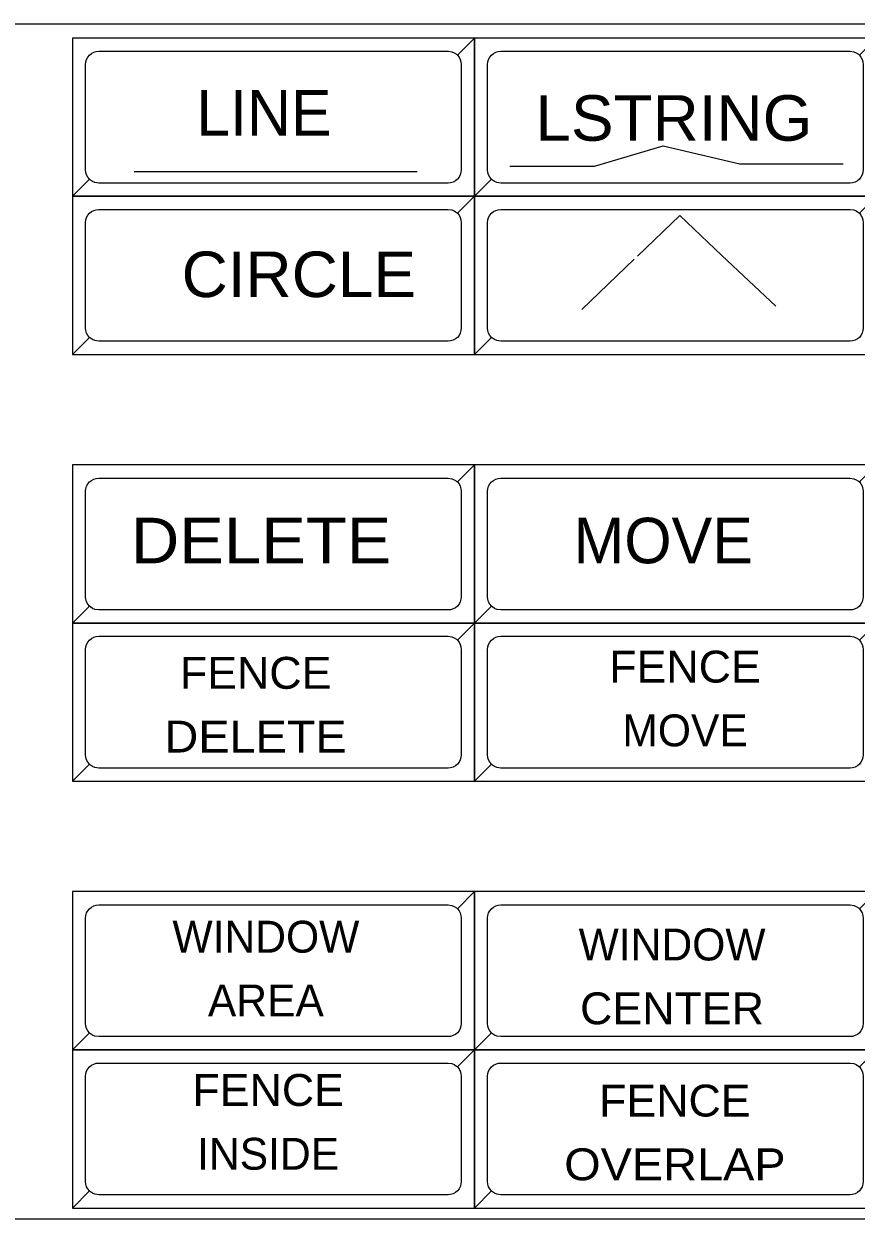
# Model space of a CAD drawing. Extents: x 16898 to 16911.6, y 15837.8 to 15842.
# Drawn here: x 16902.962 to 16904.383, y 15839.972 to 15842.012 of the extents above; entities that cross this region are included whole.
import ezdxf
from ezdxf.enums import TextEntityAlignment as Align

# ---------------------------------------------------------------- set-up
doc = ezdxf.new("R2010")
doc.units = 0
doc.header["$LTSCALE"] = 0.018
doc.linetypes.add('MEDIUM_DASHED', pattern=[4.5, 3, -1.5])
for name, color, linetype, lineweight in [('1', 7, 'Continuous', 25), ('2', 7, 'Continuous', 13), ('5', 7, 'Continuous', 13)]:
    doc.layers.add(name, color=color, linetype=linetype, lineweight=lineweight)

msp = doc.modelspace()

# ---------------------------------------------------------------- linework, layer by layer
at = {"layer": '1'}
for points in [[(16897.9955, 15839.9723), (16897.9955, 15842.0124), (16911.4764, 15842.0124), (16911.5674, 15841.9251), (16911.5674, 15840.0599), (16911.4764, 15839.9723)], [(16903.045, 15841.7183), (16903.7314, 15841.7183), (16903.7314, 15841.9883), (16903.045, 15841.9883)], [(16903.045, 15841.7183), (16903.7314, 15841.7183), (16903.7314, 15841.9883), (16903.7023, 15841.9592), (16903.7051, 15841.9558), (16903.7072, 15841.9519), (16903.7084, 15841.9477), (16903.7089, 15841.9433), (16903.7089, 15841.7633), (16903.7084, 15841.7589), (16903.7072, 15841.7547), (16903.7051, 15841.7508), (16903.7023, 15841.7474), (16903.7023, 15841.7474), (16903.6989, 15841.7446), (16903.695, 15841.7425), (16903.6908, 15841.7412), (16903.6864, 15841.7408), (16903.09, 15841.7408), (16903.0834, 15841.7418), (16903.0794, 15841.7435), (16903.0757, 15841.7459), (16903.0741, 15841.7474)], [(16903.7314, 15841.9883), (16903.045, 15841.9883), (16903.045, 15841.7183), (16903.0741, 15841.7474), (16903.0713, 15841.7508), (16903.0692, 15841.7547), (16903.0679, 15841.7589), (16903.0675, 15841.7633), (16903.0675, 15841.9433), (16903.0679, 15841.9477), (16903.0692, 15841.9519), (16903.0713, 15841.9558), (16903.0741, 15841.9592), (16903.0741, 15841.9592), (16903.0775, 15841.962), (16903.0814, 15841.9641), (16903.0856, 15841.9653), (16903.09, 15841.9658), (16903.6864, 15841.9658), (16903.693, 15841.9648), (16903.697, 15841.9631), (16903.7007, 15841.9607), (16903.7023, 15841.9592)], [(16903.7314, 15841.7183), (16904.4178, 15841.7183), (16904.4178, 15841.9883), (16903.7314, 15841.9883)], [(16903.7314, 15841.7183), (16904.4178, 15841.7183), (16904.4178, 15841.9883), (16904.3887, 15841.9592), (16904.3915, 15841.9558), (16904.3936, 15841.9519), (16904.3948, 15841.9477), (16904.3953, 15841.9433), (16904.3953, 15841.7633), (16904.3948, 15841.7589), (16904.3936, 15841.7547), (16904.3915, 15841.7508), (16904.3887, 15841.7474), (16904.3887, 15841.7474), (16904.3853, 15841.7446), (16904.3814, 15841.7425), (16904.3772, 15841.7412), (16904.3728, 15841.7408), (16903.7764, 15841.7408), (16903.7698, 15841.7418), (16903.7658, 15841.7435), (16903.7621, 15841.7459), (16903.7605, 15841.7474)], [(16904.4178, 15841.9883), (16903.7314, 15841.9883), (16903.7314, 15841.7183), (16903.7605, 15841.7474), (16903.7577, 15841.7508), (16903.7556, 15841.7547), (16903.7543, 15841.7589), (16903.7539, 15841.7633), (16903.7539, 15841.9433), (16903.7543, 15841.9477), (16903.7556, 15841.9519), (16903.7577, 15841.9558), (16903.7605, 15841.9592), (16903.7605, 15841.9592), (16903.7639, 15841.962), (16903.7678, 15841.9641), (16903.772, 15841.9653), (16903.7764, 15841.9658), (16904.3728, 15841.9658), (16904.3794, 15841.9648), (16904.3834, 15841.9631), (16904.3871, 15841.9607), (16904.3887, 15841.9592)], [(16903.045, 15841.4483), (16903.7314, 15841.4483), (16903.7314, 15841.7183), (16903.045, 15841.7183)], [(16903.045, 15841.4483), (16903.7314, 15841.4483), (16903.7314, 15841.7183), (16903.7023, 15841.6892), (16903.7051, 15841.6858), (16903.7072, 15841.6819), (16903.7084, 15841.6777), (16903.7089, 15841.6733), (16903.7089, 15841.4933), (16903.7084, 15841.4889), (16903.7072, 15841.4847), (16903.7051, 15841.4808), (16903.7023, 15841.4774), (16903.7023, 15841.4774), (16903.6989, 15841.4746), (16903.695, 15841.4725), (16903.6908, 15841.4712), (16903.6864, 15841.4708), (16903.09, 15841.4708), (16903.0834, 15841.4718), (16903.0794, 15841.4735), (16903.0757, 15841.4759), (16903.0741, 15841.4774)], [(16903.7314, 15841.7183), (16903.045, 15841.7183), (16903.045, 15841.4483), (16903.0741, 15841.4774), (16903.0713, 15841.4808), (16903.0692, 15841.4847), (16903.0679, 15841.4889), (16903.0675, 15841.4933), (16903.0675, 15841.6733), (16903.0679, 15841.6777), (16903.0692, 15841.6819), (16903.0713, 15841.6858), (16903.0741, 15841.6892), (16903.0741, 15841.6892), (16903.0775, 15841.692), (16903.0814, 15841.6941), (16903.0856, 15841.6953), (16903.09, 15841.6958), (16903.6864, 15841.6958), (16903.693, 15841.6948), (16903.697, 15841.6931), (16903.7007, 15841.6907), (16903.7023, 15841.6892)], [(16903.7314, 15841.4483), (16904.4178, 15841.4483), (16904.4178, 15841.7183), (16903.7314, 15841.7183)], [(16903.7314, 15841.4483), (16904.4178, 15841.4483), (16904.4178, 15841.7183), (16904.3887, 15841.6892), (16904.3915, 15841.6858), (16904.3936, 15841.6819), (16904.3948, 15841.6777), (16904.3953, 15841.6733), (16904.3953, 15841.4933), (16904.3948, 15841.4889), (16904.3936, 15841.4847), (16904.3915, 15841.4808), (16904.3887, 15841.4774), (16904.3887, 15841.4774), (16904.3853, 15841.4746), (16904.3814, 15841.4725), (16904.3772, 15841.4712), (16904.3728, 15841.4708), (16903.7764, 15841.4708), (16903.7698, 15841.4718), (16903.7658, 15841.4735), (16903.7621, 15841.4759), (16903.7605, 15841.4774)], [(16904.4178, 15841.7183), (16903.7314, 15841.7183), (16903.7314, 15841.4483), (16903.7605, 15841.4774), (16903.7577, 15841.4808), (16903.7556, 15841.4847), (16903.7543, 15841.4889), (16903.7539, 15841.4933), (16903.7539, 15841.6733), (16903.7543, 15841.6777), (16903.7556, 15841.6819), (16903.7577, 15841.6858), (16903.7605, 15841.6892), (16903.7605, 15841.6892), (16903.7639, 15841.692), (16903.7678, 15841.6941), (16903.772, 15841.6953), (16903.7764, 15841.6958), (16904.3728, 15841.6958), (16904.3794, 15841.6948), (16904.3834, 15841.6931), (16904.3871, 15841.6907), (16904.3887, 15841.6892)], [(16903.045, 15840.9896), (16903.7314, 15840.9896), (16903.7314, 15841.2596), (16903.045, 15841.2596)], [(16903.045, 15840.9896), (16903.7314, 15840.9896), (16903.7314, 15841.2596), (16903.7023, 15841.2305), (16903.7051, 15841.2271), (16903.7072, 15841.2232), (16903.7084, 15841.219), (16903.7089, 15841.2146), (16903.7089, 15841.0346), (16903.7084, 15841.0302), (16903.7072, 15841.026), (16903.7051, 15841.0221), (16903.7023, 15841.0187), (16903.7023, 15841.0187), (16903.6989, 15841.0159), (16903.695, 15841.0138), (16903.6908, 15841.0125), (16903.6864, 15841.0121), (16903.09, 15841.0121), (16903.0834, 15841.0131), (16903.0794, 15841.0148), (16903.0757, 15841.0172), (16903.0741, 15841.0187)], [(16903.7314, 15841.2596), (16903.045, 15841.2596), (16903.045, 15840.9896), (16903.0741, 15841.0187), (16903.0713, 15841.0221), (16903.0692, 15841.026), (16903.0679, 15841.0302), (16903.0675, 15841.0346), (16903.0675, 15841.2146), (16903.0679, 15841.219), (16903.0692, 15841.2232), (16903.0713, 15841.2271), (16903.0741, 15841.2305), (16903.0741, 15841.2305), (16903.0775, 15841.2333), (16903.0814, 15841.2354), (16903.0856, 15841.2366), (16903.09, 15841.2371), (16903.6864, 15841.2371), (16903.693, 15841.2361), (16903.697, 15841.2344), (16903.7007, 15841.232), (16903.7023, 15841.2305)], [(16903.7314, 15840.9896), (16904.4178, 15840.9896), (16904.4178, 15841.2596), (16903.7314, 15841.2596)], [(16903.7314, 15840.9896), (16904.4178, 15840.9896), (16904.4178, 15841.2596), (16904.3887, 15841.2305), (16904.3915, 15841.2271), (16904.3936, 15841.2232), (16904.3948, 15841.219), (16904.3953, 15841.2146), (16904.3953, 15841.0346), (16904.3948, 15841.0302), (16904.3936, 15841.026), (16904.3915, 15841.0221), (16904.3887, 15841.0187), (16904.3887, 15841.0187), (16904.3853, 15841.0159), (16904.3814, 15841.0138), (16904.3772, 15841.0125), (16904.3728, 15841.0121), (16903.7764, 15841.0121), (16903.7698, 15841.0131), (16903.7658, 15841.0148), (16903.7621, 15841.0172), (16903.7605, 15841.0187)], [(16904.4178, 15841.2596), (16903.7314, 15841.2596), (16903.7314, 15840.9896), (16903.7605, 15841.0187), (16903.7577, 15841.0221), (16903.7556, 15841.026), (16903.7543, 15841.0302), (16903.7539, 15841.0346), (16903.7539, 15841.2146), (16903.7543, 15841.219), (16903.7556, 15841.2232), (16903.7577, 15841.2271), (16903.7605, 15841.2305), (16903.7605, 15841.2305), (16903.7639, 15841.2333), (16903.7678, 15841.2354), (16903.772, 15841.2366), (16903.7764, 15841.2371), (16904.3728, 15841.2371), (16904.3794, 15841.2361), (16904.3834, 15841.2344), (16904.3871, 15841.232), (16904.3887, 15841.2305)], [(16903.045, 15840.7196), (16903.7314, 15840.7196), (16903.7314, 15840.9896), (16903.045, 15840.9896)], [(16903.045, 15840.7196), (16903.7314, 15840.7196), (16903.7314, 15840.9896), (16903.7023, 15840.9605), (16903.7051, 15840.9571), (16903.7072, 15840.9532), (16903.7084, 15840.949), (16903.7089, 15840.9446), (16903.7089, 15840.7646), (16903.7084, 15840.7602), (16903.7072, 15840.756), (16903.7051, 15840.7521), (16903.7023, 15840.7487), (16903.7023, 15840.7487), (16903.6989, 15840.7459), (16903.695, 15840.7438), (16903.6908, 15840.7425), (16903.6864, 15840.7421), (16903.09, 15840.7421), (16903.0834, 15840.7431), (16903.0794, 15840.7448), (16903.0757, 15840.7472), (16903.0741, 15840.7487)], [(16903.7314, 15840.9896), (16903.045, 15840.9896), (16903.045, 15840.7196), (16903.0741, 15840.7487), (16903.0713, 15840.7521), (16903.0692, 15840.756), (16903.0679, 15840.7602), (16903.0675, 15840.7646), (16903.0675, 15840.9446), (16903.0679, 15840.949), (16903.0692, 15840.9532), (16903.0713, 15840.9571), (16903.0741, 15840.9605), (16903.0741, 15840.9605), (16903.0775, 15840.9633), (16903.0814, 15840.9654), (16903.0856, 15840.9666), (16903.09, 15840.9671), (16903.6864, 15840.9671), (16903.693, 15840.9661), (16903.697, 15840.9644), (16903.7007, 15840.962), (16903.7023, 15840.9605)], [(16903.7314, 15840.7196), (16904.4178, 15840.7196), (16904.4178, 15840.9896), (16903.7314, 15840.9896)], [(16903.7314, 15840.7196), (16904.4178, 15840.7196), (16904.4178, 15840.9896), (16904.3887, 15840.9605), (16904.3915, 15840.9571), (16904.3936, 15840.9532), (16904.3948, 15840.949), (16904.3953, 15840.9446), (16904.3953, 15840.7646), (16904.3948, 15840.7602), (16904.3936, 15840.756), (16904.3915, 15840.7521), (16904.3887, 15840.7487), (16904.3887, 15840.7487), (16904.3853, 15840.7459), (16904.3814, 15840.7438), (16904.3772, 15840.7425), (16904.3728, 15840.7421), (16903.7764, 15840.7421), (16903.7698, 15840.7431), (16903.7658, 15840.7448), (16903.7621, 15840.7472), (16903.7605, 15840.7487)], [(16904.4178, 15840.9896), (16903.7314, 15840.9896), (16903.7314, 15840.7196), (16903.7605, 15840.7487), (16903.7577, 15840.7521), (16903.7556, 15840.756), (16903.7543, 15840.7602), (16903.7539, 15840.7646), (16903.7539, 15840.9446), (16903.7543, 15840.949), (16903.7556, 15840.9532), (16903.7577, 15840.9571), (16903.7605, 15840.9605), (16903.7605, 15840.9605), (16903.7639, 15840.9633), (16903.7678, 15840.9654), (16903.772, 15840.9666), (16903.7764, 15840.9671), (16904.3728, 15840.9671), (16904.3794, 15840.9661), (16904.3834, 15840.9644), (16904.3871, 15840.962), (16904.3887, 15840.9605)], [(16903.045, 15840.2612), (16903.7314, 15840.2612), (16903.7314, 15840.5312), (16903.045, 15840.5312)], [(16903.045, 15840.2612), (16903.7314, 15840.2612), (16903.7314, 15840.5312), (16903.7023, 15840.5021), (16903.7051, 15840.4987), (16903.7072, 15840.4948), (16903.7084, 15840.4906), (16903.7089, 15840.4862), (16903.7089, 15840.3062), (16903.7084, 15840.3018), (16903.7072, 15840.2976), (16903.7051, 15840.2937), (16903.7023, 15840.2903), (16903.7023, 15840.2903), (16903.6989, 15840.2875), (16903.695, 15840.2854), (16903.6908, 15840.2841), (16903.6864, 15840.2837), (16903.09, 15840.2837), (16903.0834, 15840.2847), (16903.0794, 15840.2864), (16903.0757, 15840.2888), (16903.0741, 15840.2903)], [(16903.7314, 15840.5312), (16903.045, 15840.5312), (16903.045, 15840.2612), (16903.0741, 15840.2903), (16903.0713, 15840.2937), (16903.0692, 15840.2976), (16903.0679, 15840.3018), (16903.0675, 15840.3062), (16903.0675, 15840.4862), (16903.0679, 15840.4906), (16903.0692, 15840.4948), (16903.0713, 15840.4987), (16903.0741, 15840.5021), (16903.0741, 15840.5021), (16903.0775, 15840.5049), (16903.0814, 15840.507), (16903.0856, 15840.5082), (16903.09, 15840.5087), (16903.6864, 15840.5087), (16903.693, 15840.5077), (16903.697, 15840.506), (16903.7007, 15840.5036), (16903.7023, 15840.5021)], [(16903.7314, 15840.2612), (16904.4178, 15840.2612), (16904.4178, 15840.5312), (16903.7314, 15840.5312)], [(16903.7314, 15840.2612), (16904.4178, 15840.2612), (16904.4178, 15840.5312), (16904.3887, 15840.5021), (16904.3915, 15840.4987), (16904.3936, 15840.4948), (16904.3948, 15840.4906), (16904.3953, 15840.4862), (16904.3953, 15840.3062), (16904.3948, 15840.3018), (16904.3936, 15840.2976), (16904.3915, 15840.2937), (16904.3887, 15840.2903), (16904.3887, 15840.2903), (16904.3853, 15840.2875), (16904.3814, 15840.2854), (16904.3772, 15840.2841), (16904.3728, 15840.2837), (16903.7764, 15840.2837), (16903.7698, 15840.2847), (16903.7658, 15840.2864), (16903.7621, 15840.2888), (16903.7605, 15840.2903)], [(16904.4178, 15840.5312), (16903.7314, 15840.5312), (16903.7314, 15840.2612), (16903.7605, 15840.2903), (16903.7577, 15840.2937), (16903.7556, 15840.2976), (16903.7543, 15840.3018), (16903.7539, 15840.3062), (16903.7539, 15840.4862), (16903.7543, 15840.4906), (16903.7556, 15840.4948), (16903.7577, 15840.4987), (16903.7605, 15840.5021), (16903.7605, 15840.5021), (16903.7639, 15840.5049), (16903.7678, 15840.507), (16903.772, 15840.5082), (16903.7764, 15840.5087), (16904.3728, 15840.5087), (16904.3794, 15840.5077), (16904.3834, 15840.506), (16904.3871, 15840.5036), (16904.3887, 15840.5021)], [(16903.045, 15839.9912), (16903.7314, 15839.9912), (16903.7314, 15840.2612), (16903.045, 15840.2612)], [(16903.045, 15839.9912), (16903.7314, 15839.9912), (16903.7314, 15840.2612), (16903.7023, 15840.2321), (16903.7051, 15840.2287), (16903.7072, 15840.2248), (16903.7084, 15840.2206), (16903.7089, 15840.2162), (16903.7089, 15840.0362), (16903.7084, 15840.0318), (16903.7072, 15840.0276), (16903.7051, 15840.0237), (16903.7023, 15840.0203), (16903.7023, 15840.0203), (16903.6989, 15840.0175), (16903.695, 15840.0154), (16903.6908, 15840.0141), (16903.6864, 15840.0137), (16903.09, 15840.0137), (16903.0834, 15840.0147), (16903.0794, 15840.0164), (16903.0757, 15840.0188), (16903.0741, 15840.0203)], [(16903.7314, 15840.2612), (16903.045, 15840.2612), (16903.045, 15839.9912), (16903.0741, 15840.0203), (16903.0713, 15840.0237), (16903.0692, 15840.0276), (16903.0679, 15840.0318), (16903.0675, 15840.0362), (16903.0675, 15840.2162), (16903.0679, 15840.2206), (16903.0692, 15840.2248), (16903.0713, 15840.2287), (16903.0741, 15840.2321), (16903.0741, 15840.2321), (16903.0775, 15840.2349), (16903.0814, 15840.237), (16903.0856, 15840.2382), (16903.09, 15840.2387), (16903.6864, 15840.2387), (16903.693, 15840.2377), (16903.697, 15840.236), (16903.7007, 15840.2336), (16903.7023, 15840.2321)], [(16903.7314, 15839.9912), (16904.4178, 15839.9912), (16904.4178, 15840.2612), (16903.7314, 15840.2612)], [(16903.7314, 15839.9912), (16904.4178, 15839.9912), (16904.4178, 15840.2612), (16904.3887, 15840.2321), (16904.3915, 15840.2287), (16904.3936, 15840.2248), (16904.3948, 15840.2206), (16904.3953, 15840.2162), (16904.3953, 15840.0362), (16904.3948, 15840.0318), (16904.3936, 15840.0276), (16904.3915, 15840.0237), (16904.3887, 15840.0203), (16904.3887, 15840.0203), (16904.3853, 15840.0175), (16904.3814, 15840.0154), (16904.3772, 15840.0141), (16904.3728, 15840.0137), (16903.7764, 15840.0137), (16903.7698, 15840.0147), (16903.7658, 15840.0164), (16903.7621, 15840.0188), (16903.7605, 15840.0203)], [(16904.4178, 15840.2612), (16903.7314, 15840.2612), (16903.7314, 15839.9912), (16903.7605, 15840.0203), (16903.7577, 15840.0237), (16903.7556, 15840.0276), (16903.7543, 15840.0318), (16903.7539, 15840.0362), (16903.7539, 15840.2162), (16903.7543, 15840.2206), (16903.7556, 15840.2248), (16903.7577, 15840.2287), (16903.7605, 15840.2321), (16903.7605, 15840.2321), (16903.7639, 15840.2349), (16903.7678, 15840.237), (16903.772, 15840.2382), (16903.7764, 15840.2387), (16904.3728, 15840.2387), (16904.3794, 15840.2377), (16904.3834, 15840.236), (16904.3871, 15840.2336), (16904.3887, 15840.2321)]]:
    msp.add_lwpolyline(points, close=True, dxfattribs=at)
at = {"layer": '2'}
msp.add_lwpolyline([(16897.9955, 15839.9723), (16897.9955, 15842.0124), (16911.4764, 15842.0124), (16911.5674, 15841.9251), (16911.5674, 15840.0599), (16911.4764, 15839.9723)], close=True, dxfattribs=at)
at = {"layer": '5', "lineweight": 25}
msp.add_line((16903.1503, 15841.7607), (16903.6338, 15841.7607), dxfattribs=at)
at = {"layer": '5', "linetype": 'MEDIUM_DASHED'}
for q in [(16904.0043, 15841.6107), (16904.1541, 15841.6171)]:
    msp.add_line((16904.082, 15841.6854), q, dxfattribs=at)
at = {"layer": '5'}
for p, q in [((16903.9148, 15841.5248), (16904.0043, 15841.6107)), ((16904.246, 15841.5304), (16904.1541, 15841.6171))]:
    msp.add_line(p, q, dxfattribs=at)
at = {"layer": '5', "lineweight": 25}
msp.add_lwpolyline([(16903.7917, 15841.7693), (16903.9363, 15841.7693), (16904.0538, 15841.8042), (16904.1848, 15841.7736), (16904.3608, 15841.7736)], dxfattribs=at)

# ---------------------------------------------------------------- texts
at = {"layer": '5'}
for s, height, p in [('LINE', 0.07772, (16903.3718, 15841.8217)), ('MOVE', 0.07772, (16904.0537, 15841.0917)), ('MOVE', 0.0544, (16904.0911, 15840.7793)), ('WINDOW', 0.0544, (16903.3753, 15840.4271)), ('WINDOW', 0.0544, (16904.0689, 15840.4138)), ('AREA', 0.0544, (16903.3753, 15840.3183)), ('INSIDE', 0.0544, (16903.3791, 15840.0566))]:
    msp.add_text(s, height=height, dxfattribs=at).set_placement(p, align=Align.CENTER)
for s, height, width, p in [('LSTRING', 0.07772, 1.05, (16904.072, 15841.813)), ('CIRCLE', 0.07772, 1.05, (16903.4315, 15841.5461)), ('DELETE', 0.07772, 1.1, (16903.3672, 15841.0917)), ('FENCE', 0.0544, 1.05, (16903.3578, 15840.8775)), ('FENCE', 0.0544, 1.05, (16904.091, 15840.8881)), ('DELETE', 0.0544, 1.1, (16903.3577, 15840.7687)), ('CENTER', 0.0544, 1.05, (16904.0688, 15840.3048)), ('FENCE', 0.0544, 1.05, (16903.3792, 15840.1655)), ('FENCE', 0.0544, 1.05, (16904.0736, 15840.1474)), ('OVERLAP', 0.0544, 1.1, (16904.0737, 15840.0386))]:
    msp.add_text(s, height=height, dxfattribs=dict(at, width=width)).set_placement(p, align=Align.CENTER)

doc.saveas('drawing.dxf')
